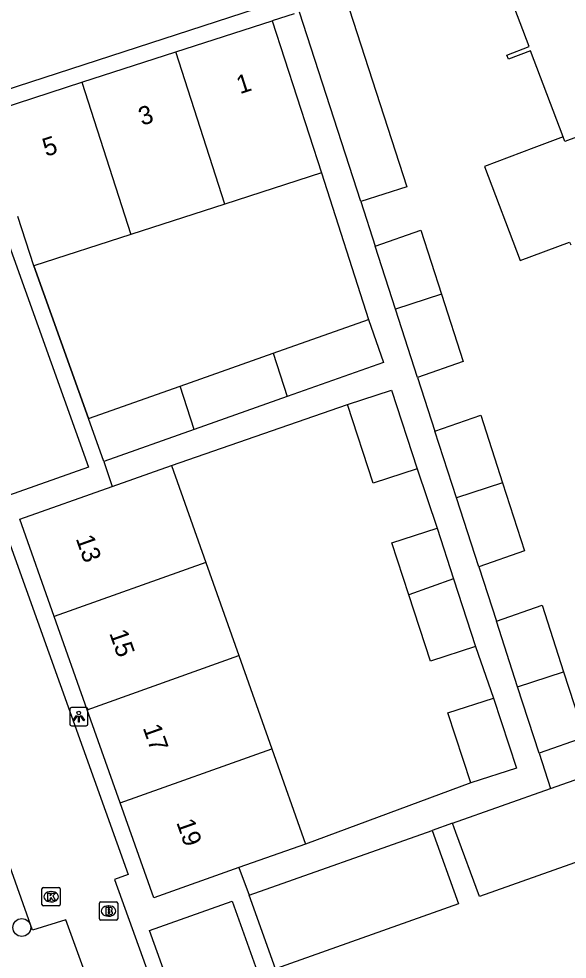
# Model space of a CAD drawing. Extents: x 159377 to 159983, y 382996 to 383595.
# Drawn here: x 159699.8 to 159729.8, y 383153 to 383204.4 of the extents above; entities that cross this region are included whole.
import ezdxf

# ---------------------------------------------------------------- set-up
doc = ezdxf.new("R2010")
doc.units = 0
for name, color, linetype in [('IMGEO_Boom', 7, 'Continuous'), ('IMGEO_Brandkraan', 7, 'Continuous'), ('IMGEO_Kolk', 7, 'Continuous'), ('IMGEO_Lichtpunt', 7, 'Continuous'), ('IMGEO_Muur', 7, 'Continuous'), ('IMGEO_Pand', 7, 'Continuous'), ('IMGEO_Pand_nummerreeks', 7, 'Continuous'), ('IMGEO_Rijbaan_lokaal_open', 7, 'Continuous'), ('IMGEO_Voetpad_open', 7, 'Continuous')]:
    doc.layers.add(name, color=color, linetype=linetype)

msp = doc.modelspace()

# ---------------------------------------------------------------- linework, layer by layer
at = {"layer": 'IMGEO_Boom'}
msp.add_circle((159699.963, 383154.774), 0.489, dxfattribs=at)
at = {"layer": 'IMGEO_Brandkraan'}
for p, q in [((159704.2, 383155.245), (159704.2, 383156.097)), ((159704.275, 383156.171), (159705.127, 383156.171)), ((159705.201, 383156.097), (159705.201, 383155.245)), ((159704.688, 383155.951), (159704.713, 383155.951)), ((159705.127, 383155.171), (159704.275, 383155.171)), ((159704.711, 383155.391), (159704.686, 383155.391))]:
    msp.add_line(p, q, dxfattribs=at)
for points in [[(159704.2, 383155.245), (159704.2, 383156.097)], [(159704.275, 383156.171), (159705.127, 383156.171)], [(159705.201, 383156.097), (159705.201, 383155.245)], [(159704.548, 383155.871), (159704.548, 383155.471), (159704.761, 383155.471)], [(159704.779, 383155.871), (159704.548, 383155.871)], [(159704.727, 383155.79), (159704.673, 383155.79), (159704.673, 383155.714)], [(159704.673, 383155.714), (159704.726, 383155.714)], [(159704.735, 383155.638), (159704.673, 383155.638), (159704.673, 383155.557)], [(159704.673, 383155.557), (159704.735, 383155.557)], [(159705.127, 383155.171), (159704.275, 383155.171)]]:
    msp.add_lwpolyline(points, dxfattribs=at)
for centre, radius, start, end in [((159704.277, 383156.095), 0.0765, 91.552, 178.448), ((159704.277, 383156.095), 0.0765, 91.552, 178.448), ((159705.125, 383156.095), 0.0765, 1.552, 88.448), ((159705.125, 383156.095), 0.0765, 1.552, 88.448), ((159704.728, 383155.752), 0.0379, 267.8285, 90.9355), ((159704.736, 383155.597), 0.0404, 269.8759, 90.5077), ((159704.767, 383155.722), 0.251, 268.6676, 293.5347), ((159704.783, 383155.726), 0.145, 59.4692, 91.5367), ((159704.808, 383155.773), 0.0922, 285.5137, 58.1501), ((159704.813, 383155.581), 0.105, 301.3115, 78.989), ((159704.277, 383155.247), 0.0765, 181.552, 268.448), ((159704.277, 383155.247), 0.0765, 181.552, 268.448), ((159705.125, 383155.247), 0.0765, 271.552, 358.448), ((159705.125, 383155.247), 0.0765, 271.552, 358.448)]:
    msp.add_arc(centre, radius, start, end, dxfattribs=at)
for centre, major_axis, ratio, start_param, end_param in [((159704.687, 383155.671), (-0.387, 0.002), 0.722429, 4.712389, 7.853982), ((159704.712, 383155.671), (-0.39, 0.002), 0.717154, 1.570796, 4.712389)]:
    msp.add_ellipse(centre, major_axis=major_axis, ratio=ratio, start_param=start_param, end_param=end_param, dxfattribs=at)
at = {"layer": 'IMGEO_Kolk'}
for p, q in [((159701.063, 383156.029), (159701.063, 383156.881)), ((159701.138, 383156.955), (159701.99, 383156.955)), ((159701.551, 383156.735), (159701.576, 383156.735)), ((159702.064, 383156.881), (159702.064, 383156.029)), ((159701.574, 383156.175), (159701.549, 383156.175)), ((159701.99, 383155.955), (159701.138, 383155.955))]:
    msp.add_line(p, q, dxfattribs=at)
for points in [[(159701.063, 383156.029), (159701.063, 383156.881)], [(159701.138, 383156.955), (159701.99, 383156.955)], [(159701.384, 383156.655), (159701.507, 383156.655), (159701.507, 383156.504), (159701.637, 383156.655), (159701.801, 383156.655), (159701.655, 383156.504), (159701.808, 383156.255), (159701.656, 383156.255), (159701.571, 383156.419), (159701.507, 383156.352), (159701.507, 383156.255), (159701.384, 383156.255), (159701.384, 383156.655)], [(159702.064, 383156.881), (159702.064, 383156.029)], [(159701.99, 383155.955), (159701.138, 383155.955)]]:
    msp.add_lwpolyline(points, dxfattribs=at)
for centre, start, end in [((159701.14, 383156.879), 91.552, 178.448), ((159701.14, 383156.879), 91.552, 178.448), ((159701.988, 383156.879), 1.552, 88.448), ((159701.988, 383156.879), 1.552, 88.448), ((159701.14, 383156.031), 181.552, 268.448), ((159701.14, 383156.031), 181.552, 268.448), ((159701.988, 383156.031), 271.552, 358.448), ((159701.988, 383156.031), 271.552, 358.448)]:
    msp.add_arc(centre, 0.0765, start, end, dxfattribs=at)
for centre, major_axis, ratio, start_param, end_param in [((159701.55, 383156.455), (-0.387, 0.002), 0.722429, 4.712389, 7.853982), ((159701.575, 383156.455), (-0.39, 0.002), 0.717154, 1.570796, 4.712389)]:
    msp.add_ellipse(centre, major_axis=major_axis, ratio=ratio, start_param=start_param, end_param=end_param, dxfattribs=at)
at = {"layer": 'IMGEO_Lichtpunt'}
for p, q in [((159703.48, 383166.792), (159702.672, 383166.792)), ((159703.48, 383166.792), (159702.672, 383166.792)), ((159702.578, 383166.697), (159702.578, 383165.89)), ((159702.578, 383166.697), (159702.578, 383165.89)), ((159703.574, 383165.89), (159703.574, 383166.697)), ((159703.574, 383165.89), (159703.574, 383166.697)), ((159702.672, 383165.796), (159703.48, 383165.796)), ((159702.672, 383165.796), (159703.48, 383165.796))]:
    msp.add_line(p, q, dxfattribs=at)
for points in [[(159702.952, 383166.361), (159702.991, 383166.333), (159702.803, 383166.071), (159702.765, 383166.098), (159702.952, 383166.361)], [(159703.054, 383166.313), (159703.101, 383166.313), (159703.101, 383165.991), (159703.054, 383165.991), (159703.054, 383166.313)], [(159703.164, 383166.333), (159703.202, 383166.36), (159703.389, 383166.098), (159703.35, 383166.07), (159703.164, 383166.333)]]:
    msp.add_lwpolyline(points, dxfattribs=at)
msp.add_circle((159703.077, 383166.495), 0.0994, dxfattribs=at)
for centre, start, end in [((159702.672, 383166.697), 90, 180), ((159702.672, 383166.697), 90, 180), ((159703.48, 383166.697), 0, 90), ((159703.48, 383166.697), 0, 90), ((159702.672, 383165.89), 180, 270), ((159702.672, 383165.89), 180, 270), ((159703.48, 383165.89), 270, 0), ((159703.48, 383165.89), 270, 360)]:
    msp.add_arc(centre, 0.0946, start, end, dxfattribs=at)
at = {"layer": 'IMGEO_Muur'}
msp.add_lwpolyline([(159703.604, 383182.586), (159700.618, 383190.933)], dxfattribs=at)
at = {"layer": 'IMGEO_Pand'}
for points in [[(159729.53, 383197.985), (159727.756, 383202.68), (159726.543, 383202.222), (159726.457, 383202.45), (159727.681, 383202.913), (159725.862, 383207.728), (159724.692, 383207.286), (159724.606, 383207.513), (159725.823, 383207.972), (159724.228, 383212.196), (159720.956, 383210.96)], [(159717.646, 383205.605), (159720.993, 383195.251), (159718.477, 383194.438)], [(159708.372, 383202.622), (159713.647, 383204.327)], [(159713.647, 383204.327), (159716.335, 383196.013)], [(159718.477, 383194.438), (159715.13, 383204.792)], [(159703.234, 383200.961), (159708.372, 383202.622)], [(159711.061, 383194.308), (159708.372, 383202.622)], [(159697.916, 383199.242), (159703.234, 383200.961)], [(159703.234, 383200.961), (159705.926, 383192.649)], [(159736.44, 383199.976), (159736.345, 383200.228), (159729.628, 383197.726), (159729.53, 383197.985)], [(159729.53, 383197.985), (159727.942, 383197.385), (159725.242, 383196.365), (159727.186, 383191.219), (159729.889, 383192.231), (159729.949, 383192.072)], [(159716.335, 383196.013), (159711.061, 383194.308)], [(159711.061, 383194.308), (159705.926, 383192.649)], [(159700.618, 383190.933), (159699.745, 383193.624)], [(159705.926, 383192.649), (159700.618, 383190.933)], [(159719.261, 383192.014), (159721.76, 383192.877), (159722.892, 383189.376)], [(159720.378, 383188.558), (159719.261, 383192.014)], [(159722.892, 383189.376), (159720.378, 383188.558)], [(159722.892, 383189.376), (159724.08, 383185.7), (159721.581, 383184.837)], [(159721.581, 383184.837), (159720.378, 383188.558)], [(159713.696, 383186.16), (159718.894, 383188.001)], [(159718.894, 383188.001), (159719.728, 383185.645), (159714.466, 383183.782)], [(159708.611, 383184.359), (159713.696, 383186.16)], [(159713.696, 383186.16), (159714.466, 383183.782)], [(159703.604, 383182.586), (159708.611, 383184.359)], [(159709.381, 383181.981), (159708.611, 383184.359)], [(159714.466, 383183.782), (159709.381, 383181.981)], [(159717.753, 383183.357), (159720.166, 383184.139), (159721.561, 383179.836)], [(159721.561, 383179.836), (159719.149, 383179.054), (159717.753, 383183.357)], [(159722.53, 383181.899), (159725.03, 383182.763), (159726.224, 383179.069)], [(159704.439, 383180.231), (159703.604, 383182.586)], [(159709.381, 383181.981), (159704.439, 383180.231)], [(159723.71, 383178.25), (159722.53, 383181.899)], [(159704.907, 383178.876), (159708.138, 383180.02)], [(159708.138, 383180.02), (159710.013, 383174.726)], [(159701.734, 383171.776), (159699.853, 383177.086), (159704.907, 383178.876)], [(159726.224, 383179.069), (159723.71, 383178.25)], [(159726.224, 383179.069), (159727.426, 383175.35), (159724.926, 383174.487)], [(159724.926, 383174.487), (159723.71, 383178.25)], [(159721.104, 383172.945), (159720.18, 383175.789), (159722.652, 383176.592)], [(159722.652, 383176.592), (159723.553, 383173.82)], [(159710.013, 383174.726), (159701.734, 383171.776)], [(159710.013, 383174.726), (159711.818, 383169.628)], [(159723.553, 383173.82), (159721.104, 383172.945)], [(159723.553, 383173.82), (159724.754, 383170.125)], [(159724.754, 383170.125), (159722.282, 383169.322), (159721.104, 383172.945)], [(159725.886, 383171.517), (159728.386, 383172.38), (159729.563, 383168.741)], [(159703.541, 383166.671), (159701.734, 383171.776)], [(159727.049, 383167.922), (159725.886, 383171.517)], [(159703.541, 383166.671), (159711.818, 383169.628)], [(159711.818, 383169.628), (159713.62, 383164.54)], [(159727.049, 383167.922), (159729.563, 383168.741)], [(159729.563, 383168.741), (159730.717, 383165.168), (159728.218, 383164.305)], [(159728.218, 383164.305), (159727.049, 383167.922)], [(159724.494, 383162.672), (159723.244, 383166.495), (159725.738, 383167.31)], [(159725.738, 383167.31), (159726.988, 383163.487), (159724.494, 383162.672)], [(159705.342, 383161.586), (159703.541, 383166.671)], [(159705.342, 383161.586), (159713.62, 383164.54)], [(159713.62, 383164.54), (159715.464, 383159.333)], [(159728.846, 383162.362), (159734.793, 383164.468), (159736.272, 383160.471), (159724.969, 383156.468), (159723.678, 383159.957), (159723.49, 383160.466)], [(159723.49, 383160.466), (159728.846, 383162.362)], [(159711.821, 383158.043), (159707.179, 383156.399), (159705.342, 383161.586)], [(159712.391, 383156.535), (159722.387, 383160.075)], [(159722.387, 383160.075), (159723.81, 383156.058), (159713.814, 383152.518)], [(159715.464, 383159.333), (159711.821, 383158.043)], [(159713.814, 383152.518), (159712.391, 383156.535)]]:
    msp.add_lwpolyline(points, dxfattribs=at)
at = {"layer": 'IMGEO_Rijbaan_lokaal_open'}
for points in [[(159691.315, 383197.108), (159691.021, 383197.927), (159713.513, 383205.238), (159711.589, 383209.95), (159720.169, 383213.044)], [(159698.578, 383176.847), (159698.668, 383176.596), (159698.957, 383176.699), (159705.773, 383157.67), (159705.026, 383157.403), (159712.83, 383135.72), (159713.607, 383133.562)], [(159710.636, 383132.475), (159709.858, 383134.615), (159702.376, 383155.2), (159700.541, 383154.623), (159693.435, 383174.689), (159693.704, 383174.782), (159693.603, 383175.063)]]:
    msp.add_lwpolyline(points, dxfattribs=at)
at = {"layer": 'IMGEO_Voetpad_open'}
for points in [[(159714.835, 383204.699), (159713.647, 383204.327)], [(159716.335, 383196.013), (159718.894, 383188.001)], [(159718.477, 383194.438), (159719.261, 383192.014)], [(159698.811, 383193.322), (159703.61, 383179.937), (159698.919, 383178.276), (159694.139, 383191.813)], [(159700.618, 383190.933), (159703.604, 383182.586)], [(159721.581, 383184.837), (159722.53, 383181.899)], [(159708.138, 383180.02), (159717.753, 383183.357)], [(159704.439, 383180.231), (159704.907, 383178.876)], [(159721.561, 383179.836), (159722.652, 383176.592)], [(159724.926, 383174.487), (159725.886, 383171.517)], [(159724.754, 383170.125), (159725.738, 383167.31)], [(159728.218, 383164.305), (159728.846, 383162.362)], [(159724.494, 383162.672), (159715.464, 383159.333)], [(159723.49, 383160.466), (159722.387, 383160.075)], [(159711.821, 383158.043), (159712.391, 383156.535)], [(159710.207, 383145.482), (159706.935, 383154.603), (159711.457, 383156.204), (159714.733, 383147.026)]]:
    msp.add_lwpolyline(points, dxfattribs=at)

# ---------------------------------------------------------------- texts
at = {"layer": 'IMGEO_Pand_nummerreeks'}
for s, rotation, p in [('1', 17.9133, (159711.88, 383200.308)), ('3', 17.9133, (159706.528, 383198.578)), ('5', 17.9133, (159701.285, 383196.883)), ('13', 289.5009, (159702.898, 383176.034)), ('15', 289.5009, (159704.73, 383170.862)), ('17', 289.5009, (159706.561, 383165.691)), ('19', 289.5009, (159708.393, 383160.519))]:
    msp.add_text(s, height=1, rotation=rotation, dxfattribs=at).set_placement(p)

doc.saveas('drawing.dxf')
